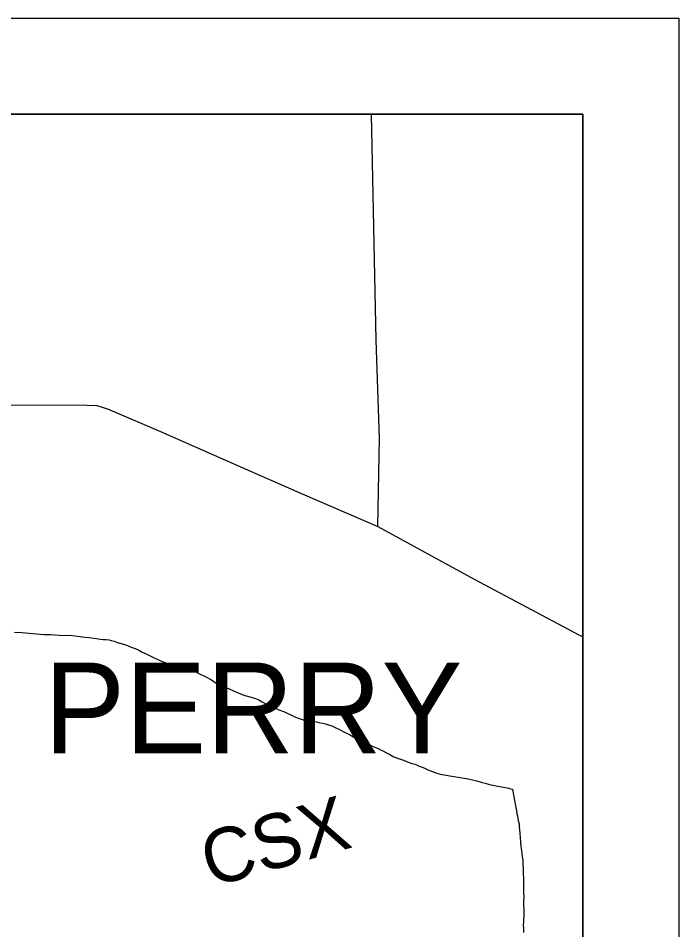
# Model space of a CAD drawing. Extents: x -59 to 82, y -3 to 49.
# Drawn here: x -48.687 to -47.998, y 48.44 to 49.391 of the extents above; entities that cross this region are included whole.
import ezdxf

# ---------------------------------------------------------------- set-up
doc = ezdxf.new("R2010")
doc.units = 0
for name, color, linetype in [('GM_X_Corporation', 7, 'Continuous'), ('GM_X_Corporation_Text', 7, 'Continuous'), ('GM_X_County_Road', 7, 'Continuous'), ('GM_X_Minor_River', 7, 'Continuous'), ('GM_X_Rail_Line_Text', 7, 'Continuous'), ('SH_Data', 7, 'Continuous')]:
    doc.layers.add(name, color=color, linetype=linetype)

msp = doc.modelspace()

# ---------------------------------------------------------------- linework, layer by layer
at = {"layer": 'GM_X_Corporation'}
for p, q in [((-48.09799, 49.29125), (-52.22423, 49.29125)), ((-48.09799, 49.29125), (-50.61637, 49.29125)), ((-48.09799, 49.29125), (-49.21726, 49.29125)), ((-48.09799, 42.49125), (-48.09799, 49.29125)), ((-48.09799, 48.03378), (-48.09799, 49.29125)), ((-48.09799, 46.29445), (-48.09799, 49.29125))]:
    msp.add_line(p, q, dxfattribs=at)
at = {"layer": 'GM_X_County_Road'}
for p, q in [((-48.31356, 49.05516), (-48.31843, 49.29125)), ((-48.31023, 48.95277), (-48.31356, 49.05516)), ((-48.73076, 48.98707), (-48.62602, 48.98778)), ((-48.62602, 48.98778), (-48.60493, 48.98707)), ((-48.60493, 48.98707), (-48.59368, 48.98355)), ((-48.59368, 48.98355), (-48.5385, 48.95999)), ((-48.5385, 48.95999), (-48.45877, 48.92488)), ((-48.31194, 48.86088), (-48.31023, 48.95277)), ((-48.45877, 48.92488), (-48.39095, 48.89491)), ((-48.39095, 48.89491), (-48.31194, 48.86088)), ((-48.31194, 48.86088), (-48.21138, 48.8059)), ((-48.21138, 48.8059), (-48.10209, 48.74773)), ((-48.10209, 48.74773), (-48.09799, 48.74559))]:
    msp.add_line(p, q, dxfattribs=at)
at = {"layer": 'GM_X_Minor_River'}
for p, q in [((-48.69074, 48.75055), (-48.6831, 48.74995)), ((-48.6831, 48.74995), (-48.67547, 48.74934)), ((-48.67547, 48.74934), (-48.66783, 48.74874)), ((-48.66783, 48.74874), (-48.6602, 48.74814)), ((-48.6602, 48.74814), (-48.65334, 48.7479)), ((-48.65334, 48.7479), (-48.64418, 48.74732)), ((-48.64418, 48.74732), (-48.6377, 48.74707)), ((-48.6377, 48.74707), (-48.63236, 48.74718)), ((-48.63236, 48.74718), (-48.62778, 48.74652)), ((-48.62778, 48.74652), (-48.62243, 48.74587)), ((-48.62243, 48.74587), (-48.61746, 48.74521)), ((-48.61746, 48.74521), (-48.61288, 48.74492)), ((-48.61288, 48.74492), (-48.6083, 48.74426)), ((-48.6083, 48.74426), (-48.60524, 48.74394)), ((-48.60524, 48.74394), (-48.60142, 48.74326)), ((-48.60142, 48.74326), (-48.59836, 48.74294)), ((-48.59836, 48.74294), (-48.59531, 48.74262)), ((-48.59531, 48.74262), (-48.59225, 48.7423)), ((-48.59225, 48.7423), (-48.58995, 48.74159)), ((-48.58995, 48.74159), (-48.58689, 48.74089)), ((-48.58689, 48.74089), (-48.58344, 48.73982)), ((-48.58344, 48.73982), (-48.57961, 48.73876)), ((-48.57961, 48.73876), (-48.57615, 48.73769)), ((-48.57615, 48.73769), (-48.57308, 48.73661)), ((-48.57308, 48.73661), (-48.56924, 48.73479)), ((-48.56924, 48.73479), (-48.56501, 48.73336)), ((-48.56501, 48.73336), (-48.56117, 48.73153)), ((-48.56117, 48.73153), (-48.5577, 48.7297)), ((-48.5577, 48.7297), (-48.55347, 48.72789)), ((-48.55347, 48.72789), (-48.54924, 48.7257)), ((-48.54924, 48.7257), (-48.545, 48.7235)), ((-48.545, 48.7235), (-48.54077, 48.72169)), ((-48.54077, 48.72169), (-48.535, 48.71914)), ((-48.535, 48.71914), (-48.5304, 48.71772)), ((-48.5304, 48.71772), (-48.52542, 48.7163)), ((-48.52542, 48.7163), (-48.51126, 48.71317)), ((-48.51126, 48.71317), (-48.50703, 48.71135)), ((-48.50703, 48.71135), (-48.50242, 48.70955)), ((-48.50242, 48.70955), (-48.49779, 48.70698)), ((-48.49779, 48.70698), (-48.49202, 48.70406)), ((-48.49202, 48.70406), (-48.48547, 48.70077)), ((-48.48547, 48.70077), (-48.47812, 48.69559)), ((-48.47812, 48.69559), (-48.46699, 48.69126)), ((-48.46699, 48.69126), (-48.45853, 48.68763)), ((-48.45853, 48.68763), (-48.45046, 48.68438)), ((-48.45046, 48.68438), (-48.44395, 48.68261)), ((-48.44395, 48.68261), (-48.43934, 48.68118)), ((-48.43934, 48.68118), (-48.43588, 48.67973)), ((-48.43588, 48.67973), (-48.43242, 48.6779)), ((-48.43242, 48.6779), (-48.42856, 48.6757)), ((-48.42856, 48.6757), (-48.42433, 48.67388)), ((-48.42433, 48.67388), (-48.4201, 48.67169)), ((-48.4201, 48.67169), (-48.4151, 48.66951)), ((-48.4151, 48.66951), (-48.40934, 48.66735)), ((-48.40934, 48.66735), (-48.40587, 48.66552)), ((-48.40587, 48.66552), (-48.40202, 48.6637)), ((-48.40202, 48.6637), (-48.39856, 48.66225)), ((-48.39856, 48.66225), (-48.39511, 48.6608)), ((-48.39511, 48.6608), (-48.39165, 48.65973)), ((-48.39165, 48.65973), (-48.38858, 48.65865)), ((-48.38858, 48.65865), (-48.38515, 48.65834)), ((-48.38515, 48.65834), (-48.38209, 48.65802)), ((-48.38209, 48.65802), (-48.37903, 48.65733)), ((-48.37903, 48.65733), (-48.37597, 48.65701)), ((-48.37597, 48.65701), (-48.37329, 48.6563)), ((-48.37329, 48.6563), (-48.36947, 48.65562)), ((-48.36947, 48.65562), (-48.36641, 48.65492)), ((-48.36641, 48.65492), (-48.36334, 48.65384)), ((-48.36334, 48.65384), (-48.35989, 48.65277)), ((-48.35989, 48.65277), (-48.35642, 48.65095)), ((-48.35642, 48.65095), (-48.3518, 48.64876)), ((-48.3518, 48.64876), (-48.34718, 48.64657)), ((-48.34718, 48.64657), (-48.34141, 48.64365)), ((-48.34141, 48.64365), (-48.33524, 48.63997)), ((-48.33524, 48.63997), (-48.32906, 48.6363)), ((-48.32906, 48.6363), (-48.32291, 48.63376)), ((-48.32291, 48.63376), (-48.316, 48.63086)), ((-48.316, 48.63086), (-48.31216, 48.62942)), ((-48.31216, 48.62942), (-48.30907, 48.62758)), ((-48.30907, 48.62758), (-48.30599, 48.62613)), ((-48.30599, 48.62613), (-48.30291, 48.62467)), ((-48.30291, 48.62467), (-48.29945, 48.62284)), ((-48.29945, 48.62284), (-48.2952, 48.62026)), ((-48.2952, 48.62026), (-48.29021, 48.61846)), ((-48.29021, 48.61846), (-48.28599, 48.61703)), ((-48.28599, 48.61703), (-48.27639, 48.61342)), ((-48.27639, 48.61342), (-48.27333, 48.61273)), ((-48.27333, 48.61273), (-48.27141, 48.61201)), ((-48.27141, 48.61201), (-48.26948, 48.61091)), ((-48.26948, 48.61091), (-48.26756, 48.61018)), ((-48.26756, 48.61018), (-48.26564, 48.60946)), ((-48.26564, 48.60946), (-48.26295, 48.60838)), ((-48.26295, 48.60838), (-48.25987, 48.60692)), ((-48.25987, 48.60692), (-48.25603, 48.60548)), ((-48.25603, 48.60548), (-48.25142, 48.60367)), ((-48.25142, 48.60367), (-48.24682, 48.60224)), ((-48.24682, 48.60224), (-48.24262, 48.60157)), ((-48.24262, 48.60157), (-48.23688, 48.60055)), ((-48.23688, 48.60055), (-48.23267, 48.59987)), ((-48.23267, 48.59987), (-48.22809, 48.59921)), ((-48.22809, 48.59921), (-48.22388, 48.59853)), ((-48.22388, 48.59853), (-48.21968, 48.59786)), ((-48.21968, 48.59786), (-48.21623, 48.59717)), ((-48.21623, 48.59717), (-48.21317, 48.59647)), ((-48.21317, 48.59647), (-48.21049, 48.59577)), ((-48.21049, 48.59577), (-48.20743, 48.59507)), ((-48.20743, 48.59507), (-48.20397, 48.594)), ((-48.20397, 48.594), (-48.19976, 48.59294)), ((-48.19976, 48.59294), (-48.19554, 48.59151)), ((-48.19554, 48.59151), (-48.18827, 48.59014)), ((-48.18827, 48.59014), (-48.18292, 48.58911)), ((-48.18292, 48.58911), (-48.17871, 48.58843)), ((-48.17871, 48.58843), (-48.17527, 48.58774)), ((-48.17527, 48.58774), (-48.17335, 48.58702)), ((-48.17335, 48.58702), (-48.17143, 48.58668)), ((-48.17143, 48.58668), (-48.17102, 48.58479)), ((-48.17102, 48.58479), (-48.17058, 48.58214)), ((-48.17058, 48.58214), (-48.17014, 48.5791)), ((-48.17014, 48.5791), (-48.1697, 48.57645)), ((-48.1697, 48.57645), (-48.16799, 48.56736)), ((-48.16799, 48.56736), (-48.16716, 48.56395)), ((-48.16716, 48.56395), (-48.16672, 48.56092)), ((-48.16672, 48.56092), (-48.16629, 48.55865)), ((-48.16629, 48.55865), (-48.16586, 48.55638)), ((-48.16586, 48.55638), (-48.16543, 48.55373)), ((-48.16543, 48.55373), (-48.1646, 48.55032)), ((-48.1646, 48.55032), (-48.16453, 48.54728)), ((-48.16453, 48.54728), (-48.16409, 48.54425)), ((-48.16409, 48.54425), (-48.16363, 48.54045)), ((-48.16363, 48.54045), (-48.16355, 48.53627)), ((-48.16355, 48.53627), (-48.16307, 48.53134)), ((-48.16307, 48.53134), (-48.16259, 48.52679)), ((-48.16259, 48.52679), (-48.16213, 48.52262)), ((-48.16213, 48.52262), (-48.16168, 48.5192)), ((-48.16168, 48.5192), (-48.16122, 48.51579)), ((-48.16122, 48.51579), (-48.16077, 48.51238)), ((-48.16077, 48.51238), (-48.16068, 48.50782)), ((-48.16068, 48.50782), (-48.16021, 48.50327)), ((-48.16021, 48.50327), (-48.16011, 48.49871)), ((-48.16011, 48.49871), (-48.16001, 48.49377)), ((-48.16001, 48.49377), (-48.1599, 48.48844)), ((-48.1599, 48.48844), (-48.15979, 48.48274)), ((-48.15979, 48.48274), (-48.16008, 48.47818)), ((-48.16008, 48.47818), (-48.15963, 48.47476)), ((-48.15959, 48.47286), (-48.15992, 48.47058)), ((-48.15992, 48.47058), (-48.15987, 48.46829)), ((-48.15987, 48.46829), (-48.15982, 48.46563)), ((-48.15982, 48.46563), (-48.15973, 48.46107)), ((-48.15963, 48.47476), (-48.15959, 48.47286)), ((-48.15973, 48.46107), (-48.15964, 48.45689)), ((-48.15964, 48.45689), (-48.15957, 48.45347)), ((-48.15984, 48.44777), (-48.16015, 48.44472)), ((-48.15957, 48.45347), (-48.15989, 48.45042)), ((-48.15989, 48.45042), (-48.15984, 48.44777)), ((-48.16015, 48.44472), (-48.16008, 48.4413)), ((-48.16008, 48.4413), (-48.16, 48.43712))]:
    msp.add_line(p, q, dxfattribs=at)
at = {"layer": 'SH_Data'}
for p, q in [((-54.99799, 49.39125), (-47.99799, 49.39125)), ((-47.99799, 49.39125), (-47.99799, 42.39125)), ((-54.89799, 49.29125), (-48.09799, 49.29125)), ((-48.09799, 49.29125), (-48.09799, 42.49125))]:
    msp.add_line(p, q, dxfattribs=at)

# ---------------------------------------------------------------- texts
at = {"layer": 'GM_X_Corporation_Text'}
msp.add_text('PERRY', height=0.094697, rotation=0.00001, dxfattribs=at).set_placement((-48.65985, 48.62401))
at = {"layer": 'GM_X_Rail_Line_Text'}
msp.add_text('CSX', height=0.056629, rotation=15.83562, dxfattribs=at).set_placement((-48.48649, 48.48379))

doc.saveas('drawing.dxf')
